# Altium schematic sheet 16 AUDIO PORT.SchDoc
size 420 x 297 mm
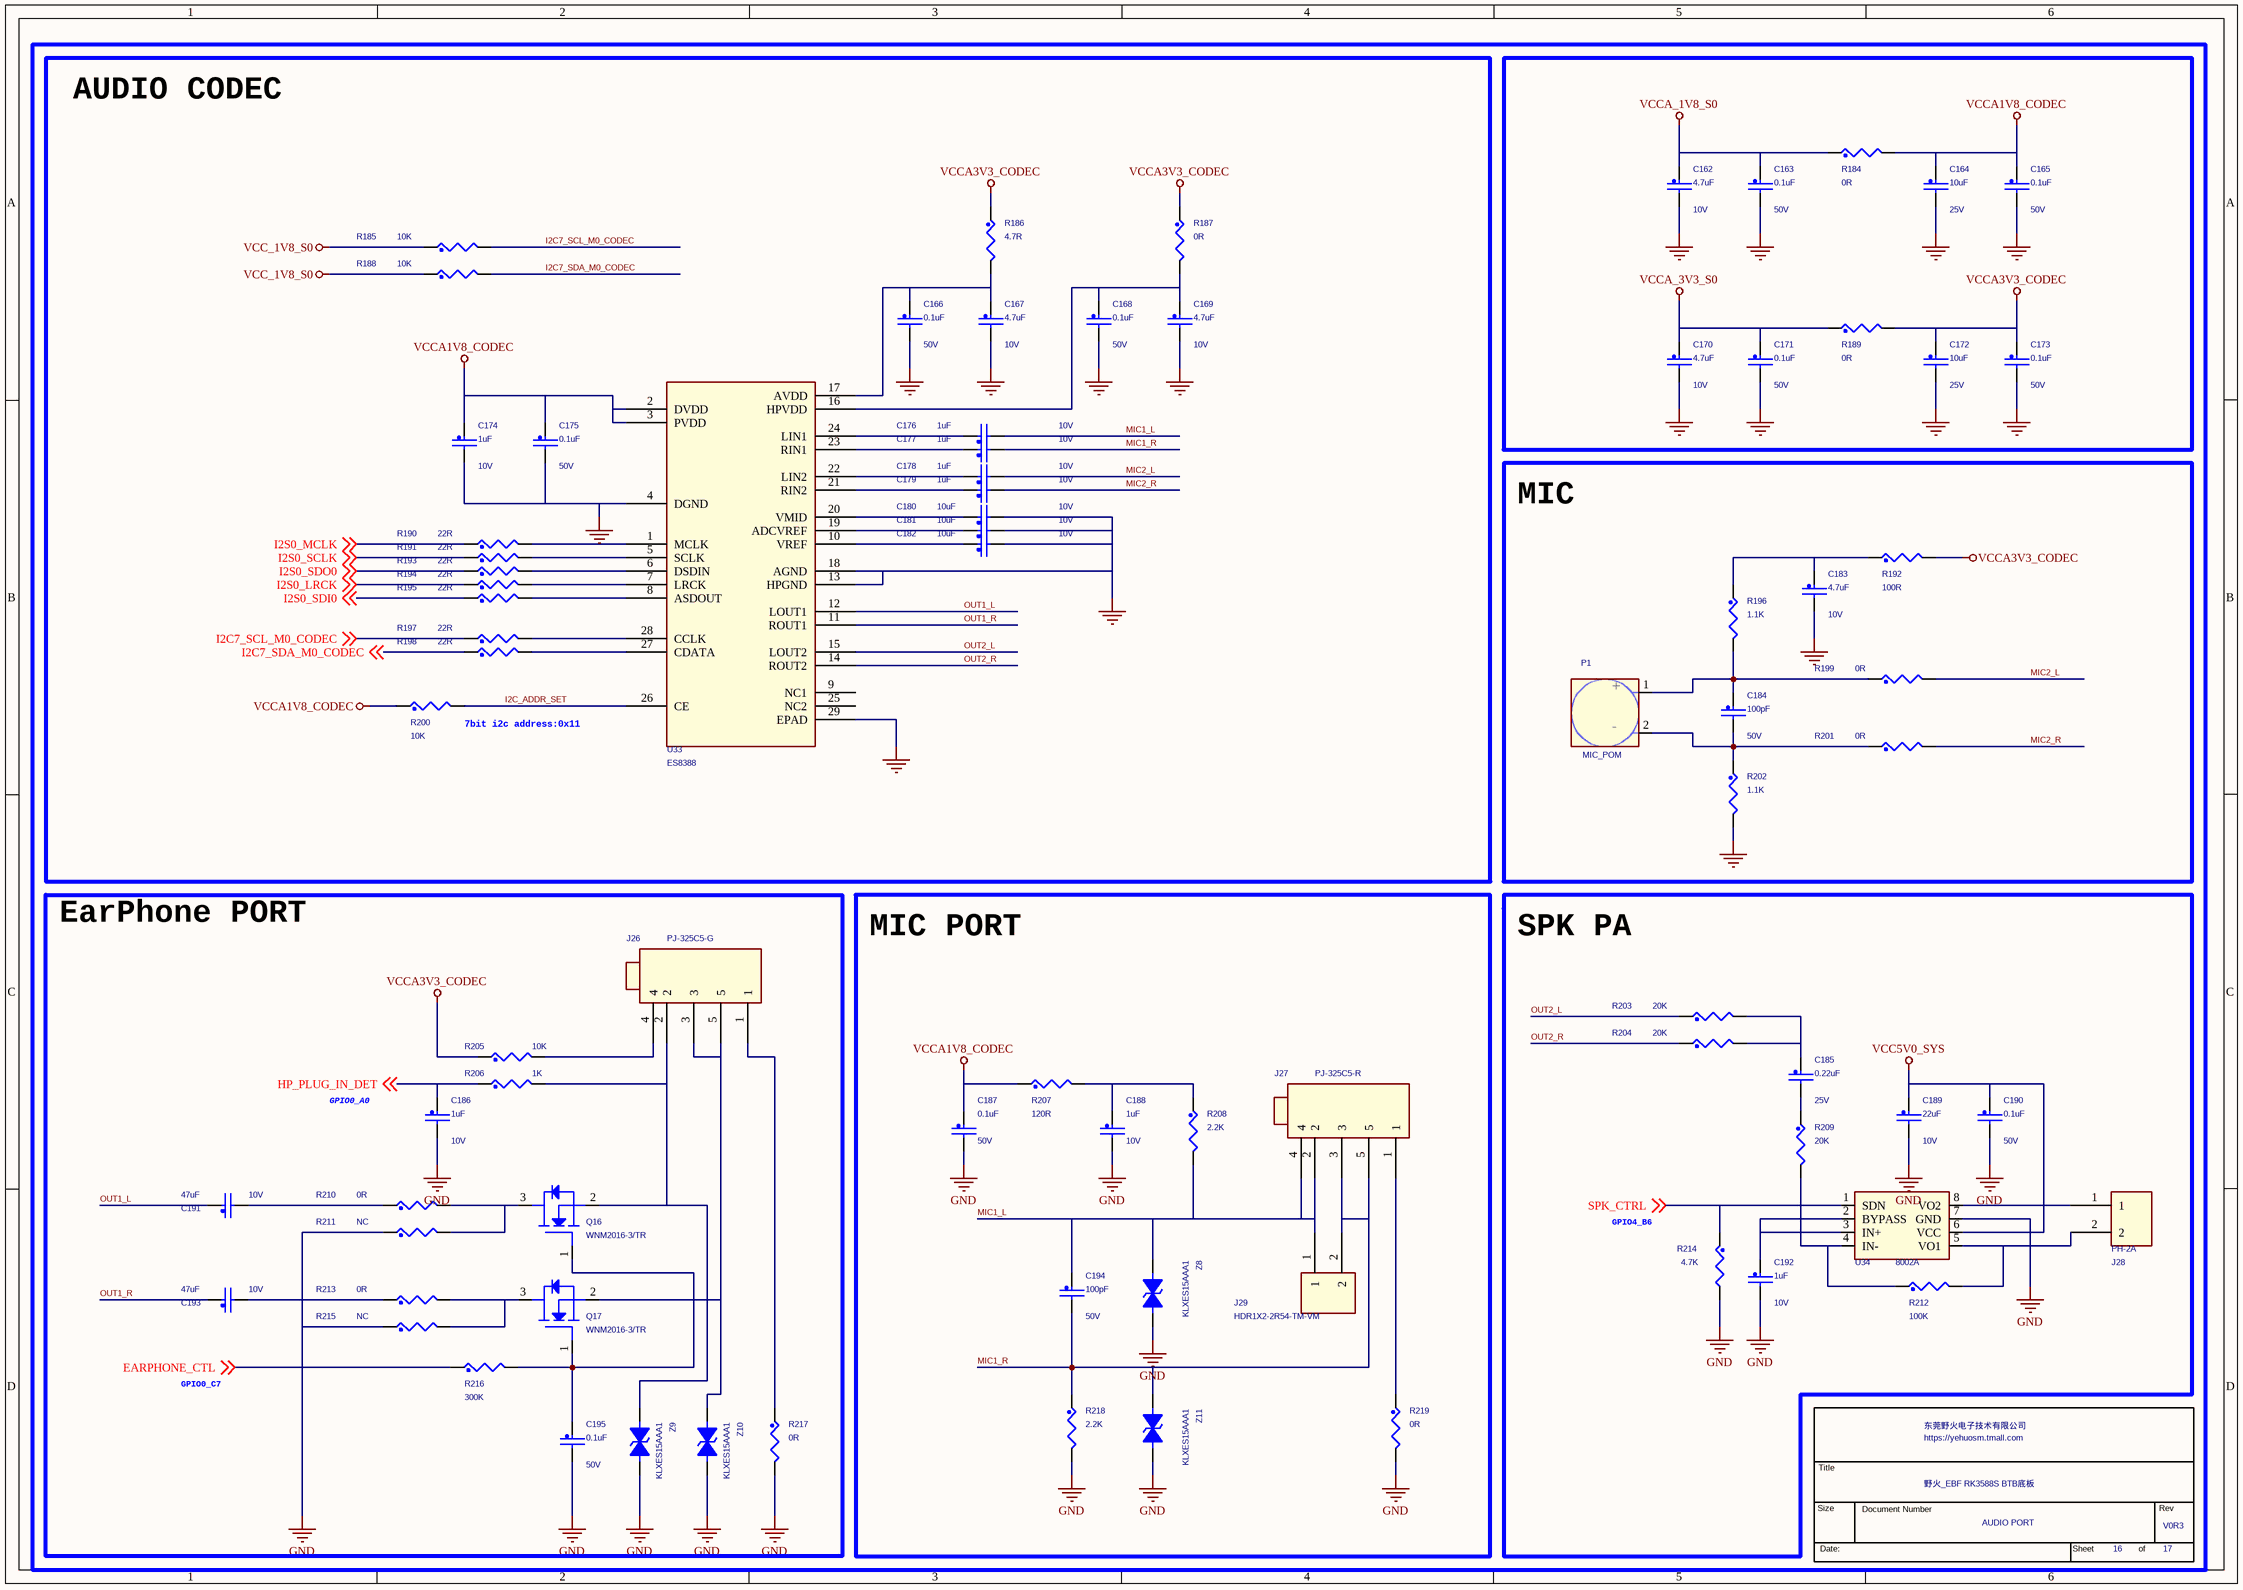
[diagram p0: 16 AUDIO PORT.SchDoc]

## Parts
*  Page Count: 17  Page Number: 16  OrgName: 东莞野火电子技术有限公司  Title: 野火_EBF RK3588S BTB底板  RevCode: V0R3  Doc: AUDIO PORT  (hidden comment: TitleBlock_YHSCH)  (graphical)
C162  4.7uF  Voltage: 10V  [C0402]
C163  0.1uF  Voltage: 50V  [C0402]
C164  10uF  Voltage: 25V  [C0603]
C165  0.1uF  Voltage: 50V  [C0402]
C166  0.1uF  Voltage: 50V  [C0402]
C167  4.7uF  Voltage: 10V  [C0402]
C168  0.1uF  Voltage: 50V  [C0402]
C169  4.7uF  Voltage: 10V  [C0402]
C170  4.7uF  Voltage: 10V  [C0402]
C171  0.1uF  Voltage: 50V  [C0402]
C172  10uF  Voltage: 25V  [C0603]
C173  0.1uF  Voltage: 50V  [C0402]
C174  1uF  Voltage: 10V  [C0402]
C175  0.1uF  Voltage: 50V  [C0402]
C176  1uF  Voltage: 10V  [C0402]
C177  1uF  Voltage: 10V  [C0402]
C178  1uF  Voltage: 10V  [C0402]
C179  1uF  Voltage: 10V  [C0402]
C180  10uF  Voltage: 10V  [C0402]
C181  10uF  Voltage: 10V  [C0402]
C182  10uF  Voltage: 10V  [C0402]
C183  4.7uF  Voltage: 10V  [C0402]
C184  100pF  Voltage: 50V  [C0402]
C185  0.22uF  Voltage: 25V  [C0402]
C186  1uF  Voltage: 10V  [C0402]
C187  0.1uF  Voltage: 50V  [C0402]
C188  1uF  Voltage: 10V  [C0402]
C189  22uF  Voltage: 10V  [C0603]
C190  0.1uF  Voltage: 50V  [C0402]
C191  47uF  Voltage: 10V  [C0805]
C192  1uF  Voltage: 10V  [C0402]
C193  47uF  Voltage: 10V  [C0805]
C194  100pF  Voltage: 50V  [C0603]
C195  0.1uF  Voltage: 50V  [C0402]
J26  PJ-325C5-G  [EAR_JACK]
J27  PJ-325C5-R  [EAR_JACK]
J28  PH-2A  [PH-1x2-2P0_l]
J29  HDR1X2-2R54-TM-VM  [HDR1X2-2R54-TM-VM]
P1  MIC_POM  [MIC2-4R00-TM]
Q16  WNM2016-3/TR  [SOT23]
Q17  WNM2016-3/TR  [SOT23]
R184  0R  [R0402]
R185  10K  [R0402]
R186  4.7R  [R0402]
R187  0R  [R0402]
R188  10K  [R0402]
R189  0R  [R0402]
R190  22R  [R0402]
R191  22R  [R0402]
R192  100R  [R0402]
R193  22R  [R0402]
R194  22R  [R0402]
R195  22R  [R0402]
R196  1.1K  [R0402]
R197  22R  [R0402]
R198  22R  [R0402]
R199  0R  [R0402]
R200  10K  [R0402]
R201  0R  [R0402]
R202  1.1K  [R0402]
R203  20K  [R0402]
R204  20K  [R0402]
R205  10K  [R0402]
R206  1K  [R0402]
R207  120R  [R0402]
R208  2.2K  [R0402]
R209  20K  [R0402]
R210  0R  [R0603]
R211  NC  [R0402]
R212  100K  [R0402]
R213  0R  [R0603]
R214  4.7K  [R0402]
R215  NC  [R0402]
R216  300K  [R0402]
R217  0R  [R0402]
R218  2.2K  [R0402]
R219  0R  [R0402]
U33  ES8388  [qfn28_0r45-4x4EP2R6X2R6]
U34  8002A  [SOP8]
Z8  KLXES15AAA1  [D0603/SMD]
Z9  KLXES15AAA1  [D0603/SMD]
Z10  KLXES15AAA1  [D0603/SMD]
Z11  KLXES15AAA1  [D0603/SMD]

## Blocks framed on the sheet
AUDIO CODEC: C166-C169 C174-C182 R185-R188 R190 R191 R193-R195 R197 R198 R200 U33
MIC: C183 C184 P1 R192 R196 R199 R201 R202
EarPhone PORT: C186 C191 C193 C195 J26 Q16 Q17 R205 R206 R210 R211 R213 R215-R217 Z9 Z10
MIC PORT: C187 C188 C194 J27 J29 R207 R208 R218 R219 Z8 Z11
SPK PA: C185 C189 C190 C192 J28 R203 R204 R209 R212 R214 U34

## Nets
GND: C162.2 C163.2 C164.2 C165.2 C166.2 C167.2 C168.2 C169.2 C170.2 C171.2 C172.2 C173.2 C174.2 C175.2 C180.2 C181.2 C182.2 C183.2 C186.2 C187.2 C188.2 C189.2 C190.2 C192.2 C195.2 R202.2 R211.1 R214.2 R215.1 R217.2 R218.2 R219.2 U33.4(DGND) U33.13(HPGND) U33.18(AGND) U33.29(EPAD) U34.7(GND) Z8.1 Z9.1 Z10.1 Z11.1
VCC5V0_SYS: C189.1 C190.1 U34.6(VCC)
VCC_1V8_S0: R185.1 R188.1
VCCA1V8_CODEC: C164.1 C165.1 C174.1 C175.1 C187.1 R184.2 R200.1 R207.1 U33.2(DVDD) U33.3(PVDD)
VCCA3V3_CODEC: C172.1 C173.1 R186.1 R187.1 R189.2 R192.2 R205.1
VCCA_1V8_S0: C162.1 C163.1 R184.1
VCCA_3V3_S0: C170.1 C171.1 R189.1
EARPHONE_CTL: R216.1 ; off-sheet EARPHONE_CTL
HP_PLUG_IN_DET: C186.1 R206.1 ; off-sheet HP_PLUG_IN_DET
I2C7_SCL_M0_CODEC: R185.2 R197.1 ; off-sheet I2C7_SCL_M0_CODEC
I2C7_SDA_M0_CODEC: R188.2 R198.1 ; off-sheet I2C7_SDA_M0_CODEC
I2C_ADDR_SET: R200.2 U33.26(CE)
I2S0_LRCK: R194.1 ; off-sheet I2S0_LRCK
I2S0_MCLK: R190.1 ; off-sheet I2S0_MCLK
I2S0_SCLK: R191.1 ; off-sheet I2S0_SCLK
I2S0_SDI0: R195.1 ; off-sheet I2S0_SDI0
I2S0_SDO0: R193.1 ; off-sheet I2S0_SDO0
MIC1_L: C176.2 C194.1 J27.2 J27.4 J29.1 R208.2 Z8.2
MIC1_R: C177.2 C194.2 J27.3 J27.5 J29.2 R218.1 Z11.2
MIC2_L: C178.2 R199.2
MIC2_R: C179.2 R201.2
OUT1_L: C191.1 U33.12(LOUT1)
OUT1_R: C193.1 U33.11(ROUT1)
OUT2_L: R203.1 U33.15(LOUT2)
OUT2_R: R204.1 U33.14(ROUT2)
SPK_CTRL: R214.1 U34.1(SDN) ; off-sheet SPK_CTRL
NetC166_1: C166.1 C167.1 R186.2 U33.17(AVDD)
NetC168_1: C168.1 C169.1 R187.2 U33.16(HPVDD)
NetC176_1: C176.1 U33.24(LIN1)
NetC177_1: C177.1 U33.23(RIN1)
NetC178_1: C178.1 U33.22(LIN2)
NetC179_1: C179.1 U33.21(RIN2)
NetC180_1: C180.1 U33.20(VMID)
NetC181_1: C181.1 U33.19(ADCVREF)
NetC182_1: C182.1 U33.10(VREF)
NetC183_1: C183.1 R192.1 R196.1
NetC184_1: C184.1 P1.1(Out) R196.2 R199.1
NetC184_2: C184.2 P1.2(GND) R201.1 R202.1
NetC185_1: C185.1 R203.2 R204.2
NetC185_2: C185.2 R209.1
NetC188_1: C188.1 R207.2 R208.1
NetC191_2: C191.2 R210.1
NetC192_1: C192.1 U34.2(BYPASS) U34.3(IN+)
NetC193_2: C193.2 R213.1
NetC195_1: C195.1 Q16.1(GATE) Q17.1(GATE) R216.2
NetJ26_1: J26.1 R217.1
NetJ26_2: J26.2 Q16.2(SOURCE) R206.2 Z9.2
NetJ26_3: J26.3 J26.5 Q17.2(SOURCE) Z10.2
NetJ26_4: J26.4 R205.2
NetJ27_1: J27.1 R219.1
NetJ28_1: J28.1 U34.8(VO2)
NetJ28_2: J28.2 R212.2 U34.5(VO1)
NetQ16_3: Q16.3(DRAIN) R210.2 R211.2
NetQ17_3: Q17.3(DRAIN) R213.2 R215.2
NetR190_2: R190.2 U33.1(MCLK)
NetR191_2: R191.2 U33.5(SCLK)
NetR193_2: R193.2 U33.6(DSDIN)
NetR194_2: R194.2 U33.7(LRCK)
NetR195_2: R195.2 U33.8(ASDOUT)
NetR197_2: R197.2 U33.28(CCLK)
NetR198_2: R198.2 U33.27(CDATA)
NetR209_2: R209.2 R212.1 U34.4(IN-)

Not connected (* = marked no-connect by the designer): U33 9(NC1) 25(NC2)

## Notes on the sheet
- (near R200) 7bit i2c address:0x11
- GPIO0_A0
- GPIO4_B6
- GPIO0_C7

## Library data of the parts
* = TitleBlock_YHSCH: Cage Code: 1
C162 C167 C170 = CAP_NP: CLASS: DISCRETE; 生命周期: 量产; 价格: 0.059058; 规格书: 国巨-贴片电容.pdf; 类别: 贴片电容0402; 品牌: 国巨; 条码: EBF29060248; 规格编号: CC0402KRX5R6BB475; 规格: 贴片电容4.7uF 10% 10V X5R 0402
C163 C165 C168 C171 C173 C195 = CAP_NP: CLASS: DISCRETE; 规格: 贴片电容0.1uF 10% 50V X5R 0402; 规格编号: 0402X104K500NT; 条码: EBF29060118; 品牌: 风华; 类别: 贴片电容0402; 规格书: 风华电容.pdf; 价格: 0.029826; 生命周期: 量产
C164 C172 = CAP_NP: CLASS: DISCRETE; 规格: 贴片电容10uF 20% 25V X5R 0603; 规格编号: CL10A106MA8NRNC; 条码: EBF29060171; 品牌: 三星; 类别: 贴片电容0603; 规格书: 三星电容.pdf; 价格: 0.109811; 生命周期: 量产
C166 C175 C190 = CAP_NP: CLASS: DISCRETE; 生命周期: 量产; 价格: 0.029826; 规格书: 风华电容.pdf; 类别: 贴片电容0402; 品牌: 风华; 条码: EBF29060118; 规格编号: 0402X104K500NT; 规格: 贴片电容0.1uF 10% 50V X5R 0402
C169 C183 = CAP_NP: CLASS: DISCRETE; 规格: 贴片电容4.7uF 10% 10V X5R 0402; 规格编号: CC0402KRX5R6BB475; 条码: EBF29060248; 品牌: 国巨; 类别: 贴片电容0402; 规格书: 国巨-贴片电容.pdf; 价格: 0.059058; 生命周期: 量产
C174 C176 C178 C192 = CAP_NP: CLASS: DISCRETE; 规格: 贴片电容1uF 10% 10V X5R 0402; 规格编号: 0402X105K100NT; 条码: EBF29060121; 品牌: 风华; 类别: 贴片电容0402; 规格书: 风华电容.pdf; 价格: 0.01191; 生命周期: 量产
C177 C179 C186 C188 = CAP_NP: CLASS: DISCRETE; 生命周期: 量产; 价格: 0.01191; 规格书: 风华电容.pdf; 类别: 贴片电容0402; 品牌: 风华; 条码: EBF29060121; 规格编号: 0402X105K100NT; 规格: 贴片电容1uF 10% 10V X5R 0402
C180 C182 = CAP_NP: CLASS: DISCRETE; 生命周期: 量产; 价格: 0.518415; 规格书: 三星电容.pdf; 类别: 贴片电容0402; 品牌: 三星; 条码: EBF29060247; 规格编号: CL05A106MP8NUB8; 规格: 贴片电容10uF 20% 10V X5R 0402
C181 = CAP_NP: CLASS: DISCRETE; 规格: 贴片电容10uF 20% 10V X5R 0402; 规格编号: CL05A106MP8NUB8; 条码: EBF29060247; 品牌: 三星; 类别: 贴片电容0402; 规格书: 三星电容.pdf; 价格: 0.518415; 生命周期: 量产
C184 = CAP_NP: CLASS: DISCRETE; 规格: 贴片电容100pF 5% 50V C0G 0402; 规格编号: GRT1555C1H101JA; 条码: EBF29060302; 品牌: 村田; 类别: 贴片电容0402; 规格书: 村田040系列贴片电容.pdf; 价格: 0.034837; 生命周期: 量产
C185 = CAP_NP: CLASS: DISCRETE; 规格: 贴片电容0.22uF 20% 25V X7R 0402; 规格编号: TCC0402X7R224K250AT; 条码: EBFCIS241220094109; 品牌: CCTC; 类别: 贴片电容0402; 规格书: CCTC_TCC0402X5R105K6R3AT; 价格: 0.0073; 生命周期: 量产; 备注: 新增0402物料
C187 = CAP_NP_Dup1: CLASS: DISCRETE; 规格: 贴片电容0.1uF 10% 50V X5R 0402; 规格编号: 0402X104K500NT; 条码: EBF29060118; 品牌: 风华; 类别: 贴片电容0402; 规格书: 风华电容.pdf; 价格: 0.029826; 生命周期: 量产
C189 = CAP_NP: CLASS: DISCRETE; 生命周期: 量产; 价格: 0.078818; 规格书: 三星电容.pdf; 类别: 贴片电容0603; 品牌: 三星; 条码: EBF29060163; 规格编号: CL10A226MP8NUNE; 规格: 贴片电容22uF 20% 10V X5R 0603
C191 = CAP_NP: CLASS: DISCRETE; 规格: 贴片电容47uF 20% 10V X5R 0805; 规格编号: 0805X476M100NT; 条码: EBF29060212; 品牌: 风华; 类别: 贴片电容0805; 规格书: 风华电容.pdf; 价格: 0.368494; 生命周期: 量产
C193 = CAP_NP: CLASS: DISCRETE; 生命周期: 量产; 价格: 0.368494; 规格书: 风华电容.pdf; 类别: 贴片电容0805; 品牌: 风华; 条码: EBF29060212; 规格编号: 0805X476M100NT; 规格: 贴片电容47uF 20% 10V X5R 0805
C194 = CAP_NP: CLASS: DISCRETE; 生命周期: 量产; 价格: 0.014181; 规格书: 风华电容.pdf; 类别: 贴片电容0603; 品牌: 风华; 条码: EBF29060132; 规格编号: 0603CG101J500NT; 规格: 贴片电容100pF 5% 50V C0G 0603
J26 = MIC_JACK: 可替代料: EBF29020024; 生命周期: 量产; 价格: 0.24; 规格书: 星坤-音频连接器.pdf; 类别: 耳机座; 品牌: 中国星坤; 规格: 音频插座 耳机插座 双声道 3.5mm耳机座 5脚 绿
J27 = MIC_JACK: 规格: 音频插座 耳机插座 双声道 3.5mm耳机座 5脚 粉; 条码: EBF29020023; 品牌: 中国星坤; 类别: 耳机座; 规格书: 星坤-音频连接器.pdf; 价格: 0.24; 生命周期: 量产
J28 = 1X2PIN: 可替代料: EBF29040005; 生命周期: 量产; 价格: 0.019031; 规格书: 博穆精密_PH2.0-A.pdf; 类别: PH连接器; 品牌: 博穆精密; 规格: 直针PH2.0-2P 间距2.0MM 拔插式 接插件
J29 = 1X2PIN: 生命周期: 量产; 价格: 0.02; 规格书: 州日_单排针_直插_2P54.pdf; 类别: 2.54mm直插单排排针; 品牌: 州日; 条码: EBF29020019; 规格编号: HDR1X2-2R54-TM-VM-BLUE; 规格: 蓝色直插单排排针 总PIN数2 间距2.54mm
P1 = MIC_POM: CLASS: IC; 生命周期: 量产; 价格: 0.868384; 规格书: 赢海_GMI4015P-2C-62db.pdf; 类别: 麦克风; 品牌: 赢海; 条码: EBFCIS221130183008; 规格编号: GMI4015P-2C-62db; 规格: 4*1.2mm咪头 双电容驻极体话筒 拾音器 工作电压1.5V-10V 灵敏度-62DB 低阻抗
Q16 = MOSFET N: 规格: N沟道MOS 导通电阻47mΩ 电流3.6A 4.5V 阈值电压(Vgs(th)@Id)1V 连续漏极电流2.9A; 条码: EBF29280014; 品牌: 韦尔; 类别: N-MOS; 规格书: WNM2016-3_TR.pdf; 备注: 立创停售
Q17 = MOSFET N: 备注: 立创停售; 规格书: WNM2016-3_TR.pdf; 类别: N-MOS; 品牌: 韦尔; 条码: EBF29280014; 规格: N沟道MOS 导通电阻47mΩ 电流3.6A 4.5V 阈值电压(Vgs(th)@Id)1V 连续漏极电流2.9A
R184 R189 = RES: CLASS: DISCRETE; 生命周期: 量产; 规格书: 合科泰-RI系列电阻.pdf; 类别: 贴片电阻0402; 品牌: 合科泰; 条码: EBF29070049; 规格编号: RI0402L000FT; 规格: 贴片电阻0R 1% 1/16W 0402
R185 R188 = RES: CLASS: DISCRETE; 价格: 0.002773; 规格: 贴片电阻10K 1% 1/16W 0402; 规格编号: 0402WGF1002TCE; 条码: EBF29070046; 品牌: 厚声; 类别: 贴片电阻0402; 规格书: 厚声-无铅厚膜电阻.pdf; 生命周期: 量产
R186 = RES: CLASS: DISCRETE; 价格: 0.003317; 规格书: 厚声-无铅厚膜电阻.pdf; 类别: 贴片电阻0402; 品牌: 厚声; 条码: EBFCIS221112135607; 规格编号: 0402WGF470KTCE; 规格: 贴片电阻4.7R 1% 1/16W 0402; 生命周期: 量产
R187 = RES: CLASS: DISCRETE; 规格书: 合科泰-RI系列电阻.pdf; 类别: 贴片电阻0402; 品牌: 合科泰; 条码: EBF29070049; 规格编号: RI0402L000FT; 规格: 贴片电阻0R 1% 1/16W 0402; 生命周期: 量产
R190 R191 R193-R195 = RES: CLASS: DISCRETE; 生命周期: 量产; 规格书: 合科泰-RI系列电阻.pdf; 类别: 贴片电阻0402; 品牌: 合科泰; 条码: EBF29070181; 规格编号: RI0402L22R0FT; 规格: 贴片电阻22R 1% 1/16W 0402
R192 = RES: CLASS: DISCRETE; 生命周期: 量产; 规格书: 合科泰-RI系列电阻.pdf; 类别: 贴片电阻0402; 品牌: 合科泰; 条码: EBF29070053; 规格编号: RI0402L1000FT; 规格: 贴片电阻100R 1% 1/16W 0402
R196 = RES: CLASS: DISCRETE; 规格: 贴片电阻1.1K 1% 1/16W 0402; 规格编号: 0402WGF1101TCE; 条码: EBFCIS221112135212; 品牌: 厚声; 类别: 贴片电阻0402; 规格书: 厚声-无铅厚膜电阻.pdf; 价格: 0.001622; 生命周期: 量产
R197 R198 = RES: CLASS: DISCRETE; 规格: 贴片电阻22R 1% 1/16W 0402; 规格编号: RI0402L22R0FT; 条码: EBF29070181; 品牌: 合科泰; 类别: 贴片电阻0402; 规格书: 合科泰-RI系列电阻.pdf; 生命周期: 量产
R199 R201 R217 R219 = RES: CLASS: DISCRETE; 规格: 贴片电阻0R 1% 1/16W 0402; 规格编号: RI0402L000FT; 条码: EBF29070049; 品牌: 合科泰; 类别: 贴片电阻0402; 规格书: 合科泰-RI系列电阻.pdf; 生命周期: 量产
R200 R205 = RES: CLASS: DISCRETE; 生命周期: 量产; 价格: 0.002773; 规格书: 厚声-无铅厚膜电阻.pdf; 类别: 贴片电阻0402; 品牌: 厚声; 条码: EBF29070046; 规格编号: 0402WGF1002TCE; 规格: 贴片电阻10K 1% 1/16W 0402
R202 = RES: CLASS: DISCRETE; 价格: 0.001622; 规格书: 厚声-无铅厚膜电阻.pdf; 类别: 贴片电阻0402; 品牌: 厚声; 条码: EBFCIS221112135212; 规格编号: 0402WGF1101TCE; 规格: 贴片电阻1.1K 1% 1/16W 0402; 生命周期: 量产
R203 R204 = RES: CLASS: DISCRETE; 规格: 贴片电阻20K 1% 1/16W 0402; 规格编号: 0402WGF2002TCE; 条码: EBF29070223; 品牌: 厚声; 类别: 贴片电阻0402; 规格书: 厚声-无铅厚膜电阻.pdf; 价格: 0.002473; 生命周期: 量产
R206 = RES: CLASS: DISCRETE; 生命周期: 量产; 规格书: 合科泰-RI系列电阻.pdf; 类别: 贴片电阻0402; 品牌: 合科泰; 条码: EBF29070050; 规格编号: RI0402L1001FT; 规格: 贴片电阻1K 1% 1/16W 0402
R207 = RES: CLASS: DISCRETE; 生命周期: 量产; 规格书: 厚声-无铅厚膜电阻.pdf; 类别: 贴片电阻0402; 品牌: 厚声; 条码: EBF29070275; 规格编号: 0402WGF1200TCE; 规格: 贴片电阻120R 1% 1/16W 0402; 价格: 0.002198
R208 = RES: CLASS: DISCRETE; 生命周期: 量产; 规格书: 合科泰-RI系列电阻.pdf; 类别: 贴片电阻0402; 品牌: 合科泰; 条码: EBF29070051; 规格编号: RI0402L2201FT; 规格: 贴片电阻2.2K 1% 1/16W 0402
R209 = RES: CLASS: DISCRETE; 价格: 0.002473; 生命周期: 量产; 规格书: 厚声-无铅厚膜电阻.pdf; 类别: 贴片电阻0402; 品牌: 厚声; 条码: EBF29070223; 规格编号: 0402WGF2002TCE; 规格: 贴片电阻20K 1% 1/16W 0402
R210 = RES: CLASS: DISCRETE; 规格: 贴片电阻0R 1% 1/10W 0603; 规格编号: RI0603L0000FT; 条码: EBF29070063; 品牌: 合科泰; 类别: 贴片电阻0603; 规格书: 合科泰-RI系列电阻.pdf; 生命周期: 量产
R211 = RES: CLASS: DISCRETE; 规格: 贴片电阻NC 预留; 条码: EBF29070087; 类别: 贴片电阻0402
R212 = RES: CLASS: DISCRETE; 生命周期: 量产; 规格书: 合科泰-RI系列电阻.pdf; 类别: 贴片电阻0402; 品牌: 合科泰; 条码: EBF29070054; 规格编号: RI0402L1003FT; 规格: 贴片电阻100K 1% 1/16W 0402
R213 = RES: CLASS: DISCRETE; 生命周期: 量产; 规格书: 合科泰-RI系列电阻.pdf; 类别: 贴片电阻0603; 品牌: 合科泰; 条码: EBF29070063; 规格编号: RI0603L0000FT; 规格: 贴片电阻0R 1% 1/10W 0603
R214 = RES: CLASS: DISCRETE; 规格: 贴片电阻4.7K 1% 1/16W 0402; 规格编号: RI0402L4701FT; 条码: EBF29070047; 品牌: 合科泰; 类别: 贴片电阻0402; 规格书: 合科泰-RI系列电阻.pdf; 生命周期: 量产
R215 = RES: CLASS: DISCRETE; 类别: 贴片电阻0402; 条码: EBF29070087; 规格: 贴片电阻NC 预留
R216 = RES: CLASS: DISCRETE; 生命周期: 量产; 规格书: 合科泰-RI系列电阻.pdf; 类别: 贴片电阻0402; 品牌: 合科泰; 条码: EBF29070220; 规格编号: RI0402L3003FT; 规格: 贴片电阻300K 1% 1/16W 0402
R218 = RES: CLASS: DISCRETE; 规格: 贴片电阻2.2K 1% 1/16W 0402; 规格编号: RI0402L2201FT; 条码: EBF29070051; 品牌: 合科泰; 类别: 贴片电阻0402; 规格书: 合科泰-RI系列电阻.pdf; 生命周期: 量产
U33 = ES8388: 价格: 3.904; 规格书: 顺芯_ES8388.pdf; 类别: 音频芯片; 品牌: 顺芯; 条码: EBFCIS221116105415; 规格: 音频接口芯片 模拟供电1.7V~3.6V 核心与IO供电1.5V~3.6V
U34 = 8002A: 生命周期: 量产; 价格: 0.475235; 规格书: 英锐芯_8002A.pdf; 类别: 音频芯片; 品牌: 英锐芯; 条码: EBF29200006; 规格: 桥式音频功率放大器 输出功率高（4Ω 1KHz）宽工作电压范围2.2V-5.5V 输出不需要外接耦合电容或上举电容 缓冲网络 反馈电阻
Z8 Z9 Z11 = DIODE BI-DIR TRIG: 规格: 用于 USB3.0、HDMI 0.5pF、5V、±15kV ESD 保护二极管; 条码: EBF29140063; 品牌: 永裕泰; 类别: 贴片ESD; 规格书: KLXES15AAA1.pdf; 价格: 0.09719; 生命周期: 量产
Z10 = DIODE BI-DIR TRIG: 生命周期: 量产; 价格: 0.09719; 规格书: KLXES15AAA1.pdf; 类别: 贴片ESD; 品牌: 永裕泰; 条码: EBF29140063; 规格: 用于 USB3.0、HDMI 0.5pF、5V、±15kV ESD 保护二极管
